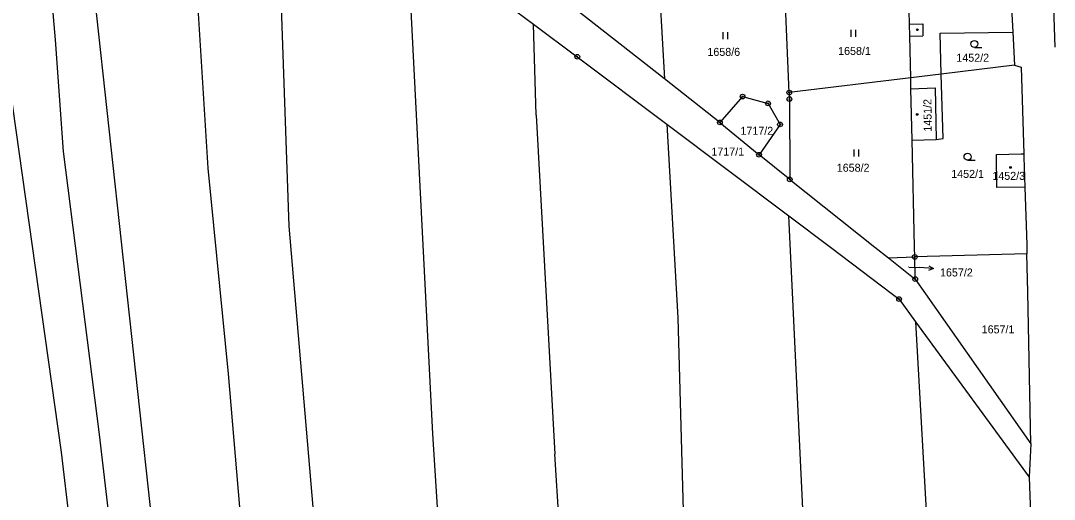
# Model space of a CAD drawing. Extents: x -763296 to -761805, y -1153670 to -1152034.
# Drawn here: x -762975 to -762755.5, y -1152536.1 to -1152434.4 of the extents above; entities that cross this region are included whole.
import ezdxf

# ---------------------------------------------------------------- set-up
doc = ezdxf.new("R2010")
doc.units = 0
for name, color, linetype in [('Vrstva 1', 7, 'Continuous'), ('Vrstva 16', 7, 'Continuous'), ('Vrstva 18', 7, 'Continuous'), ('Vrstva 19', 7, 'Continuous'), ('Vrstva 24', 7, 'Continuous'), ('Vrstva 25', 7, 'Continuous'), ('Vrstva 4', 7, 'Continuous'), ('Vrstva 6', 7, 'Continuous')]:
    doc.layers.add(name, color=color, linetype=linetype)

msp = doc.modelspace()

# ---------------------------------------------------------------- linework, layer by layer
at = {"layer": 'Vrstva 1'}
for p, q in [((-762892.96, -1152415.12), (-762866.1, -1152435.15)), ((-762756.02, -1152420.25), (-762755.36, -1152440.1)), ((-762786.26, -1152435.18), (-762786.47, -1152425.81)), ((-762838.3, -1152446.79), (-762864.9, -1152425.9)), ((-762811.78, -1152449.73), (-762812.76, -1152427.39)), ((-762764.6, -1152431.69), (-762764.32, -1152436.89)), ((-762866.1, -1152435.15), (-762856.78, -1152442.1)), ((-762786.2, -1152437.72), (-762786.26, -1152435.18)), ((-762785.99, -1152446.59), (-762786.2, -1152437.72)), ((-762779.75, -1152437.11), (-762764.32, -1152436.89)), ((-762779.51, -1152445.81), (-762779.75, -1152437.11)), ((-762764.32, -1152436.89), (-762763.95, -1152443.91)), ((-762856.78, -1152442.1), (-762837.75, -1152456.43)), ((-762763.95, -1152443.91), (-762779.51, -1152445.81)), ((-762763.95, -1152443.91), (-762762.55, -1152444.29)), ((-762762.55, -1152444.29), (-762761.96, -1152462.74)), ((-762826.5, -1152456.06), (-762838.3, -1152446.79)), ((-762785.99, -1152446.59), (-762811.78, -1152449.73)), ((-762779.51, -1152445.81), (-762785.99, -1152446.59)), ((-762785.94, -1152448.92), (-762785.99, -1152446.59)), ((-762779.12, -1152459.46), (-762779.51, -1152445.81)), ((-762811.78, -1152449.73), (-762811.73, -1152451.09)), ((-762785.69, -1152459.83), (-762785.94, -1152448.92)), ((-762821.69, -1152450.57), (-762826.5, -1152456.06)), ((-762821.69, -1152450.57), (-762816.29, -1152452)), ((-762816.29, -1152452), (-762813.74, -1152456.48)), ((-762811.73, -1152451.09), (-762811.68, -1152468.17)), ((-762865.51, -1152454.48), (-762861.53, -1152526.57)), ((-762837.75, -1152456.43), (-762811.9, -1152475.92)), ((-762826.5, -1152456.06), (-762818.2, -1152462.91)), ((-762813.74, -1152456.48), (-762818.2, -1152462.91)), ((-762785.69, -1152459.83), (-762780.56, -1152459.65)), ((-762785.17, -1152482.48), (-762785.69, -1152459.83)), ((-762780.56, -1152459.65), (-762779.12, -1152459.46)), ((-762811.68, -1152468.17), (-762818.2, -1152462.91)), ((-762767.8, -1152462.85), (-762762.53, -1152462.76)), ((-762767.67, -1152469.89), (-762767.8, -1152462.85)), ((-762762.53, -1152462.76), (-762761.96, -1152462.74)), ((-762761.96, -1152462.74), (-762761.94, -1152463.45)), ((-762761.94, -1152463.45), (-762761.74, -1152469.78)), ((-762811.68, -1152468.17), (-762793.58, -1152482.53)), ((-762761.74, -1152469.78), (-762767.67, -1152469.89)), ((-762761.74, -1152469.78), (-762761.36, -1152482.08)), ((-762811.9, -1152475.92), (-762803.04, -1152482.59)), ((-762803.04, -1152482.59), (-762789.88, -1152492.51)), ((-762793.58, -1152482.53), (-762790.74, -1152484.79)), ((-762785.12, -1152484.62), (-762785.17, -1152482.48)), ((-762761.36, -1152482.08), (-762761.3, -1152483.95)), ((-762790.74, -1152484.79), (-762785.12, -1152484.62)), ((-762790.74, -1152484.79), (-762785.02, -1152489.34)), ((-762761.3, -1152483.95), (-762785.12, -1152484.62)), ((-762785.02, -1152489.34), (-762785.12, -1152484.62)), ((-762761.14, -1152492.1), (-762761.3, -1152483.95)), ((-762785.02, -1152489.34), (-762782.83, -1152492.47)), ((-762789.88, -1152492.51), (-762788.46, -1152493.58)), ((-762788.46, -1152493.58), (-762784.94, -1152498.4)), ((-762782.83, -1152492.47), (-762760.5, -1152524.32)), ((-762760.5, -1152524.32), (-762761.14, -1152492.1)), ((-762784.94, -1152498.4), (-762760.81, -1152531.41)), ((-762760.5, -1152524.32), (-762760.81, -1152531.41)), ((-762760.81, -1152531.41), (-762756.58, -1152655.62))]:
    msp.add_line(p, q, dxfattribs=at)
at = {"layer": 'Vrstva 16'}
for p in [(-762786.37, -1152486.78), (-762781.165, -1152487.082)]:
    msp.add_line(p, (-762784.16, -1152486.91), dxfattribs=at)
msp.add_lwpolyline([(-762782.135, -1152486.526), (-762781.165, -1152487.082), (-762782.192, -1152487.524)], dxfattribs=at)
at = {"layer": 'Vrstva 24'}
for centre, radius in [((-762856.78, -1152442.1), 0.5), ((-762856.78, -1152442.1), 0.1), ((-762811.78, -1152449.73), 0.5), ((-762811.78, -1152449.73), 0.1), ((-762821.69, -1152450.57), 0.5), ((-762821.69, -1152450.57), 0.1), ((-762816.29, -1152452), 0.5), ((-762816.29, -1152452), 0.1), ((-762811.73, -1152451.09), 0.5), ((-762811.73, -1152451.09), 0.1), ((-762826.5, -1152456.06), 0.5), ((-762826.5, -1152456.06), 0.1), ((-762813.74, -1152456.48), 0.5), ((-762813.74, -1152456.48), 0.1), ((-762818.2, -1152462.91), 0.5), ((-762818.2, -1152462.91), 0.1), ((-762811.68, -1152468.17), 0.5), ((-762811.68, -1152468.17), 0.1), ((-762785.12, -1152484.62), 0.5), ((-762785.12, -1152484.62), 0.1), ((-762785.02, -1152489.34), 0.5), ((-762785.02, -1152489.34), 0.1), ((-762788.46, -1152493.58), 0.5), ((-762788.46, -1152493.58), 0.1)]:
    msp.add_circle(centre, radius, dxfattribs=at)
at = {"layer": 'Vrstva 25'}
for p, q in [((-762798.66, -1152437.89), (-762798.66, -1152436.39)), ((-762797.66, -1152437.89), (-762797.66, -1152436.39)), ((-762825.84, -1152438.36), (-762825.84, -1152436.86)), ((-762824.84, -1152438.36), (-762824.84, -1152436.86)), ((-762772.47, -1152440.13), (-762770.87, -1152440.13)), ((-762798, -1152463.3), (-762798, -1152461.8)), ((-762797, -1152463.3), (-762797, -1152461.8)), ((-762773.92, -1152464.09), (-762772.32, -1152464.09))]:
    msp.add_line(p, q, dxfattribs=at)
for centre, radius in [((-762784.6, -1152436.38), 0.175), ((-762772.47, -1152439.38), 0.75), ((-762784.61, -1152454.36), 0.175), ((-762773.92, -1152463.34), 0.75), ((-762764.8, -1152465.62), 0.175)]:
    msp.add_circle(centre, radius, dxfattribs=at)
at = {"layer": 'Vrstva 4'}
for p, q in [((-762786.26, -1152435.18), (-762783.4, -1152435.14)), ((-762783.4, -1152435.14), (-762783.42, -1152437.63)), ((-762786.2, -1152437.72), (-762783.42, -1152437.63)), ((-762785.94, -1152448.92), (-762780.78, -1152448.69)), ((-762780.78, -1152448.69), (-762780.56, -1152459.65))]:
    msp.add_line(p, q, dxfattribs=at)
at = {"layer": 'Vrstva 6'}
for p, q in [((-762935.18, -1152465.77), (-762939.63, -1152394.44)), ((-762917.97, -1152478.12), (-762920.86, -1152394.31)), ((-762887.48, -1152522.25), (-762892.96, -1152415.12)), ((-762943.84, -1152570.41), (-762960.36, -1152419.02)), ((-762967.58, -1152438.52), (-762968.78, -1152424.96)), ((-762839.29, -1152429.22), (-762838.3, -1152446.79)), ((-762865.51, -1152454.48), (-762866.1, -1152435.15)), ((-762966.34, -1152526.12), (-762978.68, -1152438.1)), ((-762965.91, -1152462.23), (-762967.58, -1152438.52)), ((-762837.75, -1152456.43), (-762835.43, -1152497.57)), ((-762958.22, -1152522.34), (-762965.91, -1152462.23)), ((-762930.82, -1152509.47), (-762935.18, -1152465.77)), ((-762806.56, -1152586.55), (-762811.9, -1152475.92)), ((-762910.79, -1152562.21), (-762917.97, -1152478.12)), ((-762835.43, -1152497.57), (-762832.79, -1152596.05)), ((-762784.94, -1152498.4), (-762778.31, -1152616.16)), ((-762925.69, -1152570.94), (-762930.82, -1152509.47)), ((-762949.29, -1152599.34), (-762958.22, -1152522.34)), ((-762880.47, -1152627.59), (-762887.48, -1152522.25)), ((-762957.5, -1152598.32), (-762966.34, -1152526.12)), ((-762856, -1152619.54), (-762861.53, -1152526.57))]:
    msp.add_line(p, q, dxfattribs=at)

# ---------------------------------------------------------------- texts
at = {"layer": 'Vrstva 16'}
msp.add_text('1657/2', height=1.7, dxfattribs=at).set_placement((-762779.767, -1152488.78))
at = {"layer": 'Vrstva 18'}
for s, p in [('1658/6', (-762829.158, -1152441.92)), ('1658/1', (-762801.4, -1152441.72)), ('1452/2', (-762776.299, -1152443.16)), ('1717/2', (-762822.14, -1152458.69)), ('1717/1', (-762828.318, -1152463.11)), ('1658/2', (-762801.692, -1152466.53)), ('1452/1', (-762777.387, -1152467.84)), ('1657/1', (-762770.923, -1152500.87))]:
    msp.add_text(s, height=1.7, dxfattribs=at).set_placement(p)
msp.add_text('1657/2', height=0.1, rotation=323.95034, dxfattribs=at).set_placement((-762786.553, -1152486.647))
at = {"layer": 'Vrstva 19'}
msp.add_text('1451/2', height=1.7, rotation=90.47004, dxfattribs=at).set_placement((-762781.531, -1152458.017))
msp.add_text('1452/3', height=1.7, dxfattribs=at).set_placement((-762768.652, -1152468.26))

doc.saveas('drawing.dxf')
